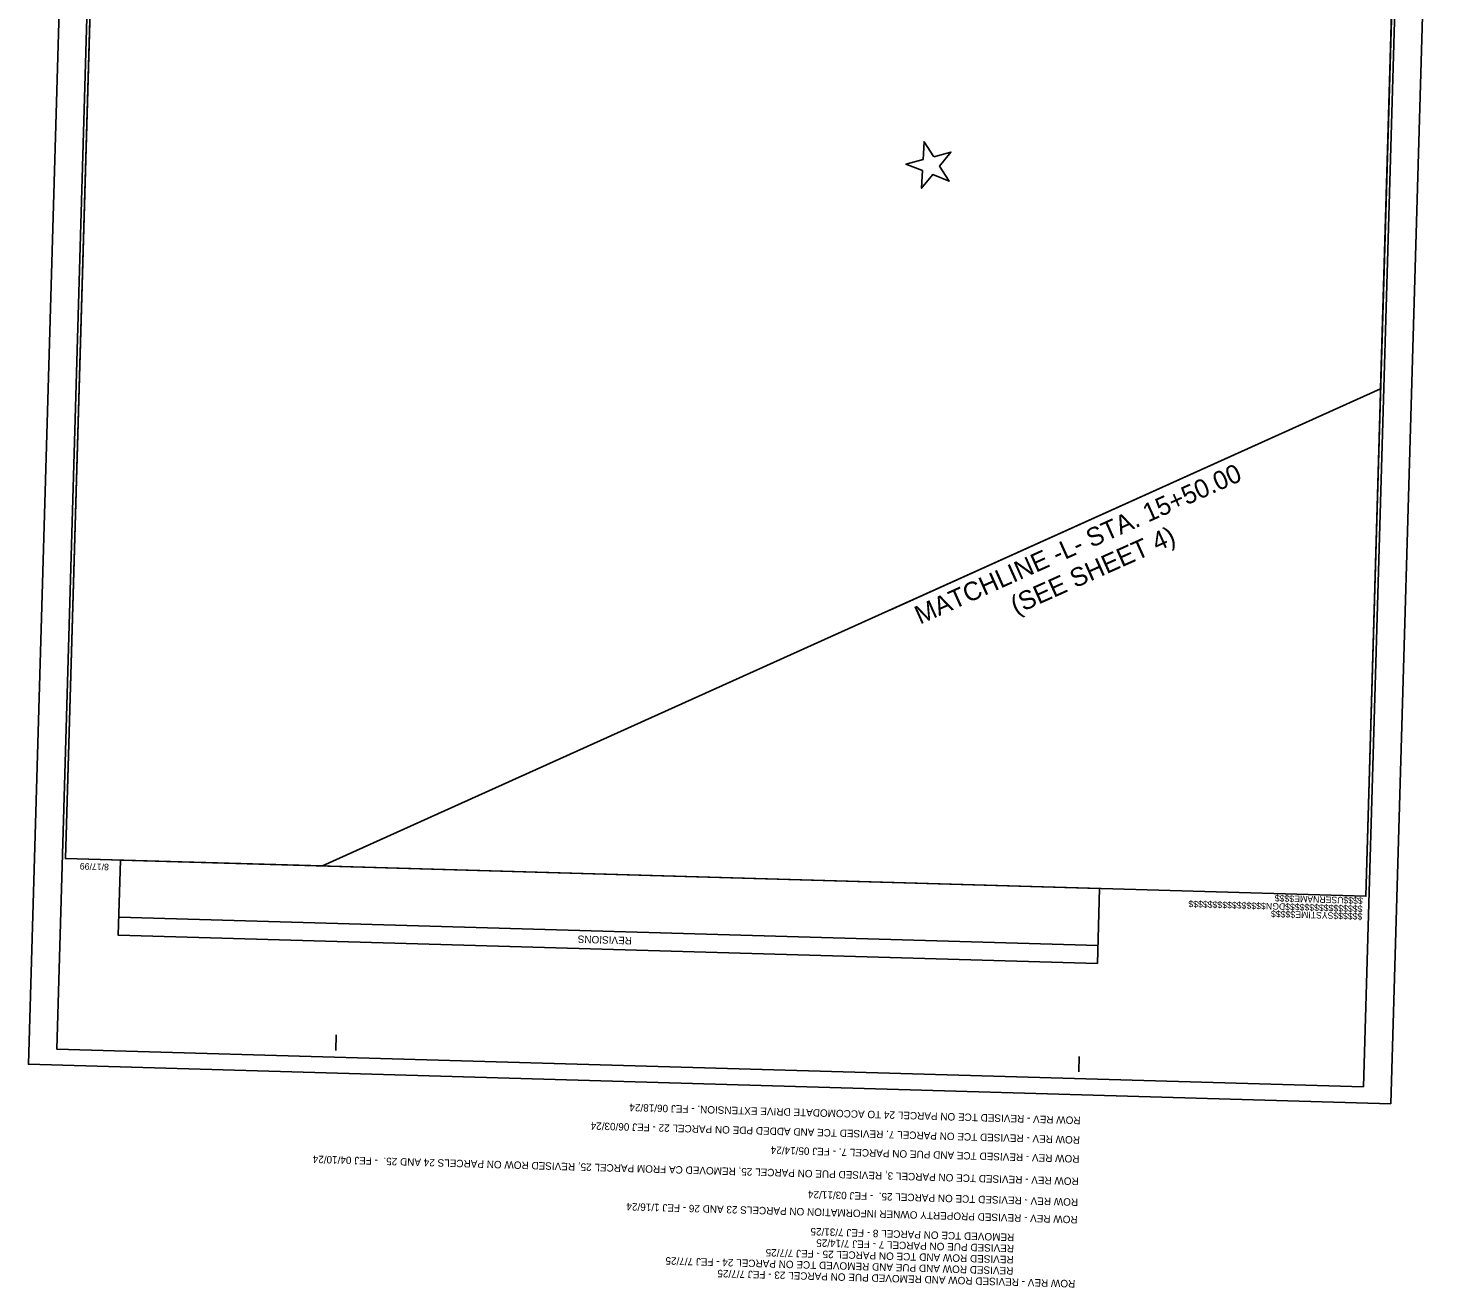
# Model space of a CAD drawing. Extents: x 2097000 to 2098148, y 684979 to 687012.
# Drawn here: x 2097000 to 2098148, y 684979 to 685995 of the extents above; entities that cross this region are included whole.
import ezdxf

# ---------------------------------------------------------------- set-up
doc = ezdxf.new("R2010")
doc.units = 0
for name, color, linetype in [('Matchline', 7, 'Continuous'), ('Matchline Text', 7, 'Continuous'), ('Prop RDY Traffic Signal CELL', 7, 'Continuous'), ('Sheet Block Revision CELL', 7, 'Continuous'), ('Sheet Layout Plan Border', 7, 'Continuous'), ('Sheet Plan And Profile CELL', 7, 'Continuous'), ('Sheet Plan CELL', 7, 'Continuous'), ('Sheet Plot Border Inside CELL', 7, 'Continuous'), ('Sheet Plot Border Outside CELL', 7, 'Continuous'), ('Sheet Profile CELL', 7, 'Continuous'), ('Sheet Profile Grid Major CELL', 7, 'Continuous')]:
    doc.layers.add(name, color=color, linetype=linetype)

msp = doc.modelspace()

# ---------------------------------------------------------------- linework, layer by layer
at = {"layer": 'Matchline'}
msp.add_line((2097694.7, 685525.6), (2098013.7, 685669.6), dxfattribs=at)
at = {"layer": 'Prop RDY Traffic Signal CELL'}
msp.add_lwpolyline([(2097730.1, 685891.7), (2097722.3, 685903.8), (2097721.5, 685889.4), (2097707.6, 685885.7), (2097721, 685880.5), (2097720.3, 685866.2), (2097729.3, 685877.3), (2097742.7, 685872.1), (2097734.9, 685884.2), (2097744, 685895.4), (2097730.1, 685891.7)], dxfattribs=at)
at = {"layer": 'Sheet Block Revision CELL'}
msp.add_line((2097862.7, 685254.7), (2097072.4, 685277.7), dxfattribs=at)
msp.add_lwpolyline([(2097862.3, 685240.2), (2097071.9, 685263.2), (2097073.7, 685323.7), (2097864, 685300.7)], close=True, dxfattribs=at)
at = {"layer": 'Sheet Layout Plan Border'}
msp.add_lwpolyline([(2098090.8, 685704.4), (2097236.9, 685319), (2097029.4, 685325), (2097067.1, 686624.4), (2097254.4, 686618.9), (2097261.8, 686618.7), (2097261, 686589.2), (2097439.3, 686584), (2097443.5, 686726.8), (2098120, 686707.2)], close=True, dxfattribs=at)
at = {"layer": 'Sheet Plot Border Inside CELL'}
msp.add_lwpolyline([(2098077, 685140.5), (2098125.4, 686806.3), (2097070.8, 686836.9), (2097022.3, 685171.1)], close=True, dxfattribs=at)
at = {"layer": 'Sheet Plot Border Outside CELL'}
msp.add_lwpolyline([(2098099.1, 685126.8), (2098148, 686810.1), (2097048.5, 686842.1), (2096999.5, 685158.8)], close=True, dxfattribs=at)
at = {"layer": 'Sheet Profile CELL'}
for p, q in [((2098078.9, 685294.5), (2098122.5, 686793.8)), ((2098078.9, 685294.5), (2098078.9, 685294.5)), ((2098078.9, 685294.5), (2098078.9, 685294.5)), ((2098078.9, 685294.5), (2098078.9, 685294.5)), ((2098078.9, 685294.5), (2098078.9, 685294.5)), ((2098078.9, 685294.5), (2098078.9, 685294.5)), ((2098078.9, 685294.5), (2098078.9, 685294.5)), ((2098078.9, 685294.5), (2098078.9, 685294.5)), ((2097247.5, 685170.1), (2097247.8, 685182.6)), ((2097847.2, 685152.7), (2097847.6, 685165.1))]:
    msp.add_line(p, q, dxfattribs=at)
msp.add_lwpolyline([(2097073, 686824.4), (2097029.4, 685325), (2098078.9, 685294.5), (2098122.5, 686793.8)], close=True, dxfattribs=at)
msp.add_lwpolyline([(2098080, 685332), (2098080, 685332)], dxfattribs=at)
at = {"layer": 'Sheet Profile Grid Major CELL'}
msp.add_line((2098053.9, 685295.2), (2098053.9, 685295.2), dxfattribs=at)

# ---------------------------------------------------------------- texts
at = {"layer": 'Matchline Text'}
for s, p in [('MATCHLINE -L- STA. 15+50.00', (2097719, 685513.8)), ('(SEE SHEET 4)', (2097796.4, 685521.8))]:
    msp.add_text(s, height=15, rotation=24.122, dxfattribs=at).set_placement(p)
at = {"layer": 'Sheet Block Revision CELL'}
for s, p in [('REVISIONS', (2097486.6, 685261.6)), ('ROW REV - REVISED TCE ON PARCEL 24 TO ACCOMODATE DRIVE EXTENSION. - FEJ 06/18/24', (2097848.7, 685116.4)), ('ROW REV - REVISED TCE ON PARCEL 7. REVISED TCE AND ADDED PDE ON PARCEL 22 - FEJ 06/03/24', (2097848.2, 685100.6)), ('ROW REV - REVISED TCE AND PUE ON PARCEL 7. - FEJ 05/14/24', (2097847.8, 685085.3)), ('ROW REV - REVISED TCE ON PARCEL 3, REVISED PUE ON PARCEL 25, REMOVED CA FROM PARCEL 25, REVISED ROW ON PARCELS 24 AND 25.  - FEJ 04/10/24', (2097847.2, 685067.2)), ('ROW REV - REVISED TCE ON PARCEL 25.  - FEJ 03/11/24', (2097846.7, 685050.4)), ('ROW REV - REVISED PROPERTY OWNER INFORMATION ON PARCELS 23 AND 26 - FEJ 1/16/24', (2097846.3, 685036.3)), (' REMOVED TCE ON PARCEL 8 - FEJ 7/31/25', (2097797.4, 685021.9)), (' REVISED PUE ON PARCEL 7 - FEJ 7/14/25', (2097797.2, 685012.9)), (' REVISED ROW AND TCE ON PARCEL 25 - FEJ 7/7/25', (2097796.9, 685003.9)), (' REVISED ROW AND PUE AND REMOVED TCE ON PARCEL 24 - FEJ 7/7/25', (2097796.7, 684994.9)), ('ROW REV - REVISED ROW AND REMOVED PUE ON PARCEL 23 - FEJ 7/7/25', (2097844.4, 684984.5))]:
    msp.add_text(s, height=6, rotation=178.3348, dxfattribs=at).set_placement(p)
at = {"layer": 'Sheet Plan And Profile CELL'}
msp.add_text('8/17/99', height=5.25, rotation=178.3348, dxfattribs=at).set_placement((2097064.5, 685320.7))
at = {"layer": 'Sheet Plan CELL'}
for s, p in [('$$$$USERNAME$$$$', (2098076.5, 685293.5)), ('$$$$$$$$$$$$$$$$DGN$$$$$$$$$$$$$$$$', (2098076.3, 685286.9)), ('$$$$$$SYSTIME$$$$$', (2098076.2, 685280.8))]:
    msp.add_text(s, height=5.25, rotation=178.3348, dxfattribs=at).set_placement(p)

doc.saveas('drawing.dxf')
